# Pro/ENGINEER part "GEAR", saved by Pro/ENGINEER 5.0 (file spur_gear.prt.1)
Units: Inch lbm Second (Pro/E Default); INCH, POUND, SECS

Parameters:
  DESCRIPTION = "GEAR"

Other parameters: T, X, Y, Z, R, ANG, S, XC, YC

Other named items: ROOT_DIA, BASE_DIA, PITCH_DIA, MEASURE, RIGHT, TOP, FRONT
